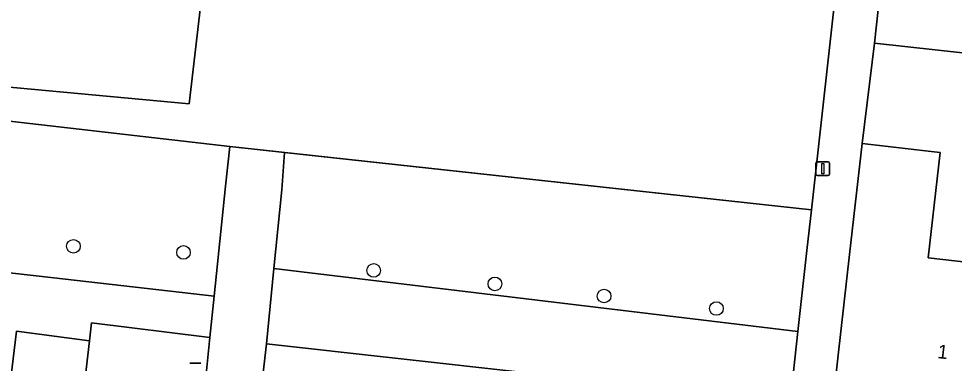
# Model space of a CAD drawing. Extents: x 162082 to 163401, y 388089 to 388636.
# Drawn here: x 162647.3 to 162714.5, y 388179.9 to 388204.7 of the extents above; entities that cross this region are included whole.
import ezdxf

# ---------------------------------------------------------------- set-up
doc = ezdxf.new("R2010")
doc.units = 0
for name, color, linetype in [('IMGEO_Boom', 7, 'Continuous'), ('IMGEO_Erf', 7, 'Continuous'), ('IMGEO_Groenvoorziening', 7, 'Continuous'), ('IMGEO_Hek', 7, 'Continuous'), ('IMGEO_Lichtmast', 7, 'Continuous'), ('IMGEO_Pand', 7, 'Continuous'), ('IMGEO_Pand_nummerreeks', 7, 'Continuous'), ('IMGEO_Voetpad_gesloten', 7, 'Continuous'), ('IMGEO_Voetpad_open', 7, 'Continuous')]:
    doc.layers.add(name, color=color, linetype=linetype)

msp = doc.modelspace()

# ---------------------------------------------------------------- linework, layer by layer
at = {"layer": 'IMGEO_Boom'}
for centre in [(162651.189, 388188.291), (162659.101, 388187.849), (162672.771, 388186.553), (162681.487, 388185.582), (162689.335, 388184.709), (162697.41, 388183.81)]:
    msp.add_circle(centre, 0.489, dxfattribs=at)
at = {"layer": 'IMGEO_Erf'}
msp.add_lwpolyline([(162717.722, 388201.931), (162708.768, 388202.91), (162707.88, 388195.679), (162712.849, 388195.115), (162713.504, 388195.041), (162712.643, 388187.449), (162720.225, 388186.589)], dxfattribs=at)
at = {"layer": 'IMGEO_Groenvoorziening'}
for points in [[(162708.484, 388229.124), (162656.335, 388234.801), (162656.279, 388234.387), (162663.577, 388233.565), (162659.497, 388198.553), (162635.737, 388200.74), (162640.847, 388243.608), (162655.066, 388242.035), (162655.191, 388243.088), (162656.169, 388251.807), (162656.21, 388252.334), (162602.483, 388258.384), (162596.208, 388203.054), (162600.069, 388202.629), (162612.235, 388201.026), (162637.2, 388198.38), (162662.426, 388195.481), (162666.371, 388195.051), (162704.239, 388190.913), (162708.41, 388228.518)], [(162703.915, 388187.998), (162704.239, 388190.913), (162666.371, 388195.051), (162666.162, 388192.347), (162665.601, 388186.69), (162703.27, 388182.157)], [(162647.106, 388182.185), (162652.348, 388181.486), (162652.494, 388182.789), (162661.001, 388181.725), (162661.305, 388184.711), (162649.768, 388186.014), (162618.336, 388189.565), (162618.361, 388188.104), (162611.227, 388125.114), (162645.375, 388121.434), (162646.317, 388129.731), (162640.919, 388131.009)], [(162703.27, 388182.157), (162665.601, 388186.69), (162665.064, 388181.271), (162702.709, 388177.08)], [(162652.348, 388181.486), (162647.106, 388182.185), (162640.919, 388131.009), (162646.317, 388129.731)]]:
    msp.add_lwpolyline(points, close=True, dxfattribs=at)
for points in [[(162662.109, 388192.62), (162662.426, 388195.481), (162637.2, 388198.38), (162612.235, 388201.026), (162600.069, 388202.629), (162599.927, 388201.374), (162599.507, 388201.296), (162599.398, 388200.146), (162598.866, 388194.531), (162612.9, 388194.32)], [(162618.336, 388189.565), (162649.768, 388186.014), (162661.305, 388184.711), (162662.109, 388192.62)]]:
    msp.add_lwpolyline(points, dxfattribs=at)
at = {"layer": 'IMGEO_Hek'}
for points in [[(162714.001, 388278.243), (162710.804, 388250), (162708.484, 388229.124), (162704.239, 388190.917)], [(162704.239, 388190.917), (162662.426, 388195.481), (162637.2, 388198.38), (162612.235, 388201.026), (162600.069, 388202.629), (162596.208, 388203.054)]]:
    msp.add_lwpolyline(points, dxfattribs=at)
at = {"layer": 'IMGEO_Lichtmast'}
for p, q in [((162704.657, 388194.374), (162705.447, 388194.374)), ((162705.447, 388194.374), (162704.657, 388194.374)), ((162704.557, 388193.474), (162704.557, 388194.274)), ((162704.557, 388194.274), (162704.557, 388193.474)), ((162705.547, 388194.274), (162705.547, 388193.474)), ((162705.547, 388193.474), (162705.547, 388194.274)), ((162705.447, 388193.374), (162704.657, 388193.374)), ((162704.657, 388193.374), (162705.447, 388193.374)), ((162659.554, 388179.868), (162660.344, 388179.868)), ((162660.344, 388179.868), (162659.554, 388179.868))]:
    msp.add_line(p, q, dxfattribs=at)
msp.add_lwpolyline([(162704.977, 388194.249), (162705.127, 388194.249), (162705.127, 388193.499), (162704.977, 388193.499), (162704.977, 388194.249)], dxfattribs=at)
for centre, start, end in [((162704.657, 388194.274), 90, 180), ((162704.657, 388194.274), 90, 180), ((162705.447, 388194.274), 0, 90), ((162705.447, 388194.274), 360, 90), ((162704.657, 388193.474), 180, 270), ((162704.657, 388193.474), 180, 270), ((162705.447, 388193.474), 270, 0), ((162705.447, 388193.474), 270, 0)]:
    msp.add_arc(centre, 0.1, start, end, dxfattribs=at)
at = {"layer": 'IMGEO_Pand'}
for points in [[(162722.353, 388193.838), (162724.237, 388211.019), (162717.271, 388211.798), (162717.33, 388212.333), (162717.055, 388212.363), (162716.996, 388211.825), (162709.83, 388212.61), (162708.768, 388202.91), (162717.722, 388201.931), (162716.902, 388194.435), (162721.873, 388193.891)], [(162721.626, 388186.43), (162720.225, 388186.589), (162712.643, 388187.449), (162713.504, 388195.041), (162712.849, 388195.115), (162707.88, 388195.679), (162706.975, 388187.702), (162705.936, 388178.541), (162713.185, 388177.719), (162713.124, 388177.183), (162713.4, 388177.152), (162713.462, 388177.697), (162717.454, 388177.245), (162717.537, 388177.981), (162720.421, 388177.654), (162720.279, 388176.403), (162720.485, 388176.38)]]:
    msp.add_lwpolyline(points, close=True, dxfattribs=at)
at = {"layer": 'IMGEO_Voetpad_gesloten'}
msp.add_lwpolyline([(162663.577, 388233.565), (162656.279, 388234.387), (162655.072, 388234.523), (162654.187, 388234.622), (162655.066, 388242.035), (162640.847, 388243.608), (162635.737, 388200.74), (162659.497, 388198.553)], close=True, dxfattribs=at)
at = {"layer": 'IMGEO_Voetpad_open'}
for points in [[(162729.94, 388342.515), (162721.188, 388343.447), (162720.121, 388331.869), (162719.528, 388326.805), (162714.003, 388278.163), (162713.987, 388278.025), (162710.804, 388250), (162708.484, 388229.124), (162708.41, 388228.518), (162704.239, 388190.913), (162703.915, 388187.998), (162703.27, 388182.157), (162702.709, 388177.08), (162705.689, 388176.792), (162705.936, 388178.541), (162706.975, 388187.702), (162707.88, 388195.679), (162708.768, 388202.91), (162709.83, 388212.61), (162710.107, 388214.707), (162711.489, 388227.332), (162713.938, 388250), (162717.461, 388280.321), (162722.517, 388279.851)], [(162665.601, 388186.69), (162666.162, 388192.347), (162666.371, 388195.051), (162662.426, 388195.481), (162662.109, 388192.62), (162661.305, 388184.711), (162661.001, 388181.725), (162660.458, 388176.442)], [(162664.665, 388177.732), (162665.064, 388181.271), (162665.601, 388186.69)], [(162660.458, 388176.442), (162661.001, 388181.725), (162652.494, 388182.789), (162652.348, 388181.486), (162646.317, 388129.731), (162645.375, 388121.434), (162644.798, 388116.081), (162643.205, 388116.25), (162642.758, 388111.326), (162642.688, 388111.281)], [(162705.689, 388176.792), (162702.709, 388177.08), (162665.064, 388181.271), (162664.665, 388177.732)]]:
    msp.add_lwpolyline(points, dxfattribs=at)

# ---------------------------------------------------------------- texts
at = {"layer": 'IMGEO_Pand_nummerreeks'}
msp.add_text('1', height=1, rotation=353.52558, dxfattribs=at).set_placement((162713.266, 388180.244))

doc.saveas('drawing.dxf')
